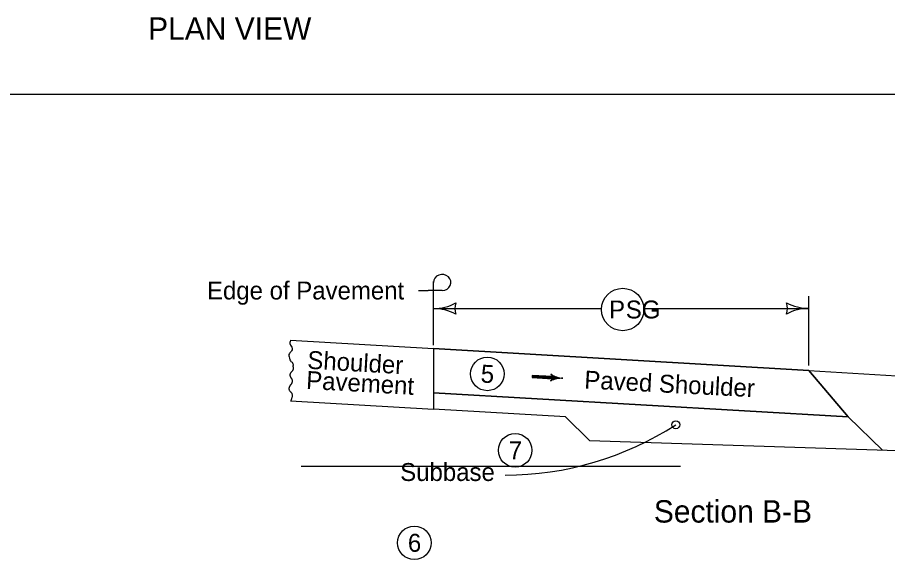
# Model space of a CAD drawing. Extents: x 6410 to 81668, y 3928 to 11667.
# Drawn here: x 11038 to 11815, y 8934 to 9419 of the extents above; entities that cross this region are included whole.
import ezdxf

# ---------------------------------------------------------------- set-up
doc = ezdxf.new("R2010")
doc.units = 0
for name, color, linetype in [('dsnCellElements', 7, 'Continuous'), ('dsnShtPlotShapeBatchPrint', 7, 'Continuous'), ('dsnStdBlockModified', 7, 'Continuous'), ('Level 11', 7, 'Continuous'), ('Level 14', 7, 'Continuous'), ('Level 7', 7, 'Continuous')]:
    doc.layers.add(name, color=color, linetype=linetype)

msp = doc.modelspace()

# ---------------------------------------------------------------- linework, layer by layer
at = {"layer": 'dsnCellElements'}
for p, q in [((11409.68, 9162.01), (11409.68, 9182.87)), ((11396.31, 9174.85), (11405, 9174.85)), ((11417.49, 9174.85), (11405, 9174.85)), ((11409.68, 9126.07), (11409.68, 9162.01)), ((11516.07, 9096.96), (11497.86, 9098.01)), ((11515.96, 9096.03), (11515.96, 9096.03)), ((11516.08, 9097.97), (11516.08, 9097.97))]:
    msp.add_line(p, q, dxfattribs=at)
for points in [[(11516.09, 9097.91), (11497.93, 9098.96), (11497.8, 9097.07), (11515.96, 9096.03), (11516.02, 9097.64), (11498.15, 9098.73), (11498.09, 9097.23), (11515.58, 9096.29), (11515.7, 9097.41), (11498.38, 9098.47), (11498.36, 9097.47), (11515.37, 9096.49), (11515.46, 9097.19), (11498.57, 9098.25), (11498.55, 9097.69), (11515.16, 9096.75)], [(11515.69, 9099.16), (11516.38, 9097.99), (11516.36, 9096.35), (11515.6, 9094.95), (11518.36, 9095.81), (11521.55, 9096.46), (11522.45, 9096.6), (11520.21, 9097.15), (11516.98, 9098.38), (11516.04, 9098.91), (11516.16, 9095.4), (11521.11, 9096.62), (11516.47, 9098.2), (11516.48, 9095.78), (11519.88, 9096.71), (11516.88, 9097.57), (11516.65, 9096.18), (11518.81, 9096.69), (11517.22, 9097.2), (11517.08, 9096.54), (11517.87, 9096.7)]]:
    msp.add_lwpolyline(points, dxfattribs=at)
for centre, major_axis, start_param, end_param in [((11417.49, 9181.99), (-7.81, 0), 1.570796, 6.283185), ((11512.3, 9097.18), (3.88, 0), 5.202895, 7.237436), ((11524.57, 9076.18), (22.17, 0), 1.537172, 2.061295), ((11527.36, 9116.6), (-22.17, 0), 0.954258, 1.478381)]:
    msp.add_ellipse(centre, major_axis=major_axis, ratio=0.913811, start_param=start_param, end_param=end_param, dxfattribs=at)
at = {"layer": 'dsnShtPlotShapeBatchPrint'}
for p, q in [((11744.9, 9107.99), (11744.9, 9169.67)), ((11409.68, 9158.69), (11559.68, 9158.69)), ((11597.5, 9158.84), (11744.9, 9158.84))]:
    msp.add_line(p, q, dxfattribs=at)
msp.add_circle((11578.6, 9157.87), 18.93, dxfattribs=at)
for centre, radius, start, end in [((11409.68, 9201.19), 42.5, 270, 298.07249), ((11409.68, 9116.19), 42.5, 61.92751, 90), ((11445.32, 9158.69), 16.42, 162.26665, 197.73335), ((11709.27, 9158.84), 16.42, 342.26665, 17.73335), ((11744.9, 9201.34), 42.5, 241.92751, 270), ((11744.9, 9116.34), 42.5, 90, 118.07249), ((11473.09, 9291.91), 282.03, 270.13198, 302.84273)]:
    msp.add_arc(centre, radius, start, end, dxfattribs=at)
at = {"layer": 'dsnStdBlockModified'}
for p, q in [((11282.22, 9130.34), (11409.68, 9122.93)), ((11409.68, 9122.93), (11409.68, 9068.91)), ((11409.68, 9122.93), (11744.82, 9103.44)), ((11744.82, 9103.44), (11409.68, 9122.93)), ((11409.68, 9122.93), (11409.68, 9083.33)), ((11744.82, 9103.44), (11779.86, 9061.99)), ((11744.82, 9103.44), (11879.66, 9095.05)), ((11779.86, 9061.99), (11744.82, 9103.44)), ((11779.86, 9061.99), (11409.68, 9083.33)), ((11409.68, 9083.33), (11779.86, 9061.99)), ((11282.25, 9076.32), (11409.68, 9068.91)), ((11527.52, 9062.12), (11409.68, 9068.91)), ((11527.52, 9062.12), (11548.86, 9040.91)), ((11779.86, 9061.99), (11810.39, 9032.36)), ((11548.86, 9040.91), (12032.2, 9025.11)), ((11291.63, 9018.01), (11630.13, 9018.01))]:
    msp.add_line(p, q, dxfattribs=at)
msp.add_circle((11457.8, 9100.36), 15, dxfattribs=at)
for points in [[(11282.22, 9130.34), (11281.71, 9126.74), (11282.76, 9125.23), (11283.62, 9122.93), (11283.02, 9120.87), (11281.11, 9118.5), (11280.59, 9116.6), (11281.11, 9114.3), (11281.98, 9111.93), (11283.02, 9111.21), (11284.4, 9108.68), (11284.39, 9107.84)], [(11282.43, 9090.73), (11282.64, 9090.97), (11282.84, 9091.23), (11283.19, 9091.79), (11283.47, 9092.39), (11283.59, 9092.69), (11283.69, 9093.01), (11283.82, 9093.63), (11283.87, 9094.25), (11283.82, 9094.83), (11283.76, 9095.11), (11283.72, 9095.25), (11283.68, 9095.38), (11283.47, 9095.75), (11283.19, 9096.12), (11282.89, 9096.48), (11282.64, 9096.88), (11282.5, 9097.16), (11282.36, 9097.45), (11282.1, 9098.02), (11281.9, 9098.59), (11281.83, 9098.88), (11281.77, 9099.18), (11281.76, 9099.31), (11281.76, 9099.43), (11281.91, 9100.21), (11282.12, 9100.73), (11282.38, 9101.24), (11282.82, 9101.88), (11283.34, 9102.42), (11283.86, 9102.97), (11284.09, 9103.27), (11284.29, 9103.61), (11284.49, 9104.09), (11284.65, 9104.56), (11284.75, 9105.04), (11284.78, 9105.28), (11284.8, 9105.4), (11284.81, 9105.51), (11284.76, 9106.02), (11284.61, 9106.54), (11284.56, 9106.66), (11284.5, 9106.79), (11284.45, 9106.92), (11284.43, 9107.05), (11284.39, 9107.84)], [(11282.43, 9090.73), (11282.21, 9090.49), (11281.97, 9090.26), (11281.73, 9090.01), (11281.55, 9089.75), (11281.41, 9089.46), (11281.27, 9089.18), (11281.01, 9088.61), (11280.9, 9088.32), (11280.8, 9088.04), (11280.73, 9087.74), (11280.7, 9087.6), (11280.68, 9087.45), (11280.69, 9086.93), (11280.82, 9086.42), (11281.03, 9085.9), (11281.29, 9085.39), (11281.73, 9084.75), (11282.25, 9084.21), (11282.77, 9083.66), (11283, 9083.36), (11283.2, 9083.01), (11283.6, 9082.07), (11283.71, 9081.59), (11283.72, 9081.11), (11283.68, 9080.83), (11283.63, 9080.54), (11283.58, 9080.25), (11283.51, 9079.97), (11283.2, 9078.82), (11283.02, 9078.21), (11282.82, 9077.61), (11282.6, 9077.02), (11282.47, 9076.73), (11282.33, 9076.44), (11282.25, 9076.32)]]:
    msp.add_spline(points, degree=3, dxfattribs=at)
at = {"layer": 'Level 11'}
msp.add_line((12308.76, 9349.9), (10153.18, 9349.9), dxfattribs=at)
at = {"layer": 'Level 14'}
msp.add_circle((11626.04, 9054.96), 3.54, dxfattribs=at)
at = {"layer": 'Level 7'}
for centre in [(11457.8, 9100.36), (11482.65, 9032.07), (11392.6, 8949.46)]:
    msp.add_circle(centre, 15, dxfattribs=at)

# ---------------------------------------------------------------- texts
at = {"layer": 'dsnCellElements'}
for s, height, p in [('PLAN VIEW', 20, (11155.04, 9398.79)), ('Edge of Pavement', 16, (11207.55, 9166.85)), ('Subbase', 16, (11380.03, 9004.69)), ('Section B-B', 20, (11606.42, 8967.53))]:
    msp.add_text(s, height=height, dxfattribs=at).set_placement(p)
for s, rotation, p in [('Shoulder', 356.73462, (11296.81, 9105)), ('Paved Shoulder ', 357.0678, (11544.08, 9087.33)), ('Pavement', 356.73462, (11295.79, 9087.03))]:
    msp.add_text(s, height=16, rotation=rotation, dxfattribs=at).set_placement(p)
at = {"layer": 'dsnShtPlotShapeBatchPrint'}
for s, p in [('P', (11566.47, 9149.87)), ('SG', (11581.38, 9149.87))]:
    msp.add_text(s, height=16, dxfattribs=at).set_placement(p)
at = {"layer": 'Level 7'}
msp.add_text('5', height=16, rotation=356.69973, dxfattribs=at).set_placement((11451.58, 9092.7))
for s, p in [('7', (11476.94, 9024.07)), ('6', (11386.89, 8941.46))]:
    msp.add_text(s, height=16, dxfattribs=at).set_placement(p)

doc.saveas('drawing.dxf')
